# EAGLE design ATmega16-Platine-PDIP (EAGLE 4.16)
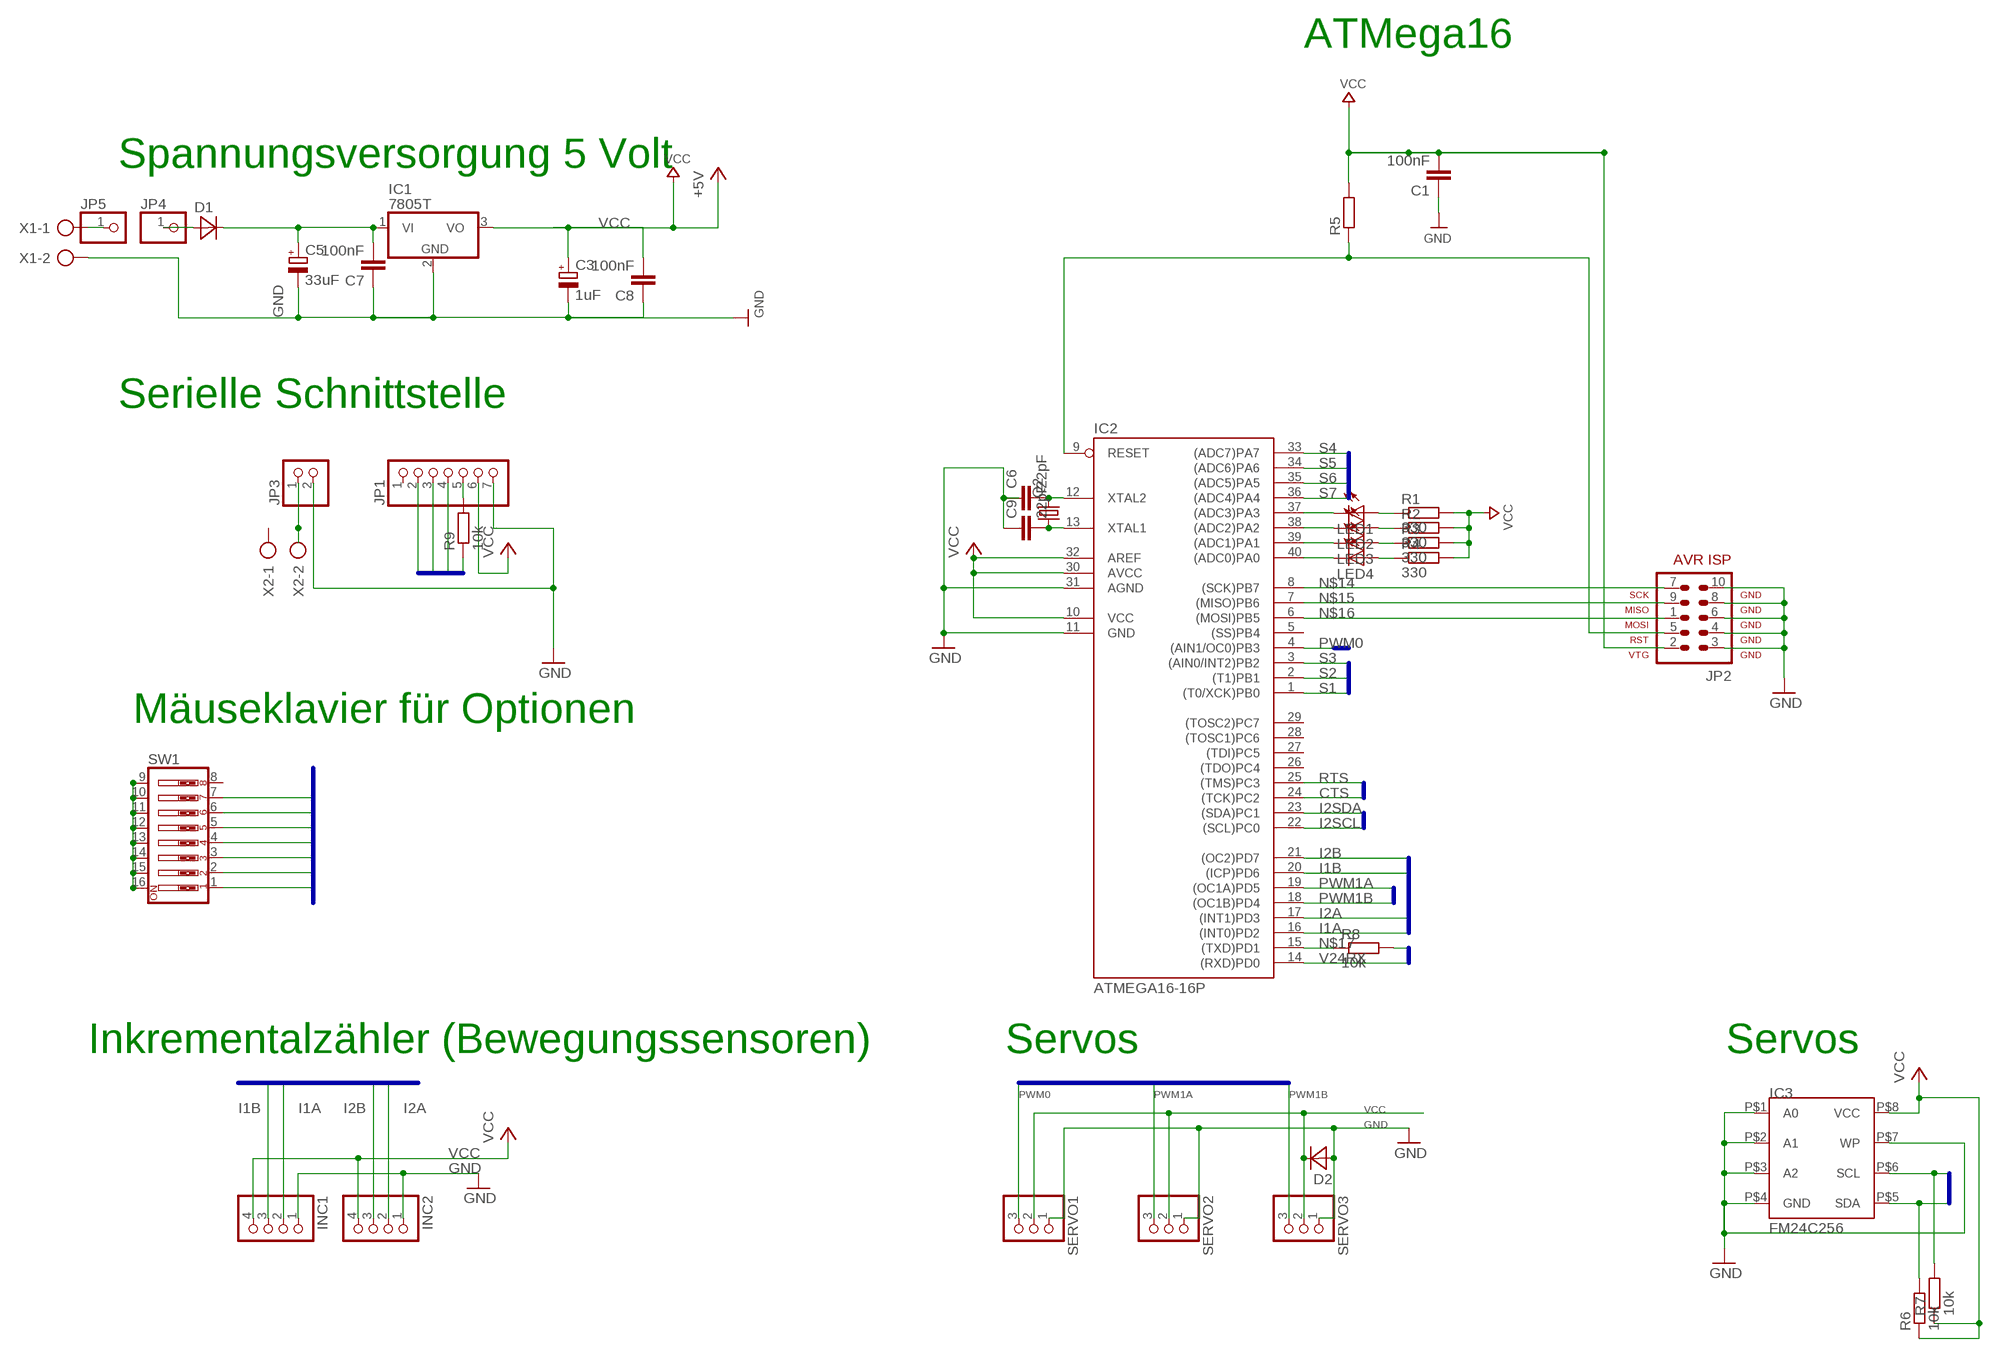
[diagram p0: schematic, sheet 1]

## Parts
C1  100nF  C2.5/2  [C2.5-2]
C3  1uF  CPOL-EUE2.5-5  [E2,5-5]
C5  33uF  CPOL-EUE2.5-5  [E2,5-5]
C6  22pF  C2.5/2  [C2.5-2]
C7  100nF  C2.5/2  [C2.5-2]
C8  100nF  C2.5/2  [C2.5-2]
C9  22pF  C2.5/2  [C2.5-2]
D1  DIODE-10  [D-10]
D2  DIODE-10  [D-10]
IC1  7805T  [TO220H]
IC2  ATMEGA16-16P  [DIL40]
IC3  FM24C256  [EIAJ-SOIC-8]
INC1  PINHD-1X4  [1X04]
INC2  PINHD-1X4  [1X04]
JP1  PINHD-1X7  [1X07]
JP2  AVR-ISP-10  [AVR-ISP-10]
JP3  PINHD-1X2  [1X02]
JP4  PINHD-1X1  [1X01]
JP5  PINHD-1X1  [1X01]
LED1  LED5MM  [LED5MM]
LED2  LED5MM  [LED5MM]
LED3  LED5MM  [LED5MM]
LED4  LED5MM  [LED5MM]
Q2  CRYTALHC49S  [HC49/S]
R1  330  R-EU_M1206  [M1206]
R2  330  R-EU_M1206  [M1206]
R3  330  R-EU_M1206  [M1206]
R4  330  R-EU_M1206  [M1206]
R5  R-EU_M1206  [M1206]
R6  10k  R-EU_M1206  [M1206]
R7  10k  R-EU_M1206  [M1206]
R8  10k  R-EU_M1206  [M1206]
R9  10k  R-EU_M1206  [M1206]
SERVO1  PINHD-1X3  [1X03]
SERVO2  PINHD-1X3  [1X03]
SERVO3  PINHD-1X3  [1X03]
SW1  SW_DIP-8  [EDG-08]
X1  AK500/2  [AK500/2]
X2  AK500/2  [AK500/2]

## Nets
/RESET: IC2.9(RESET) JP2.5 R5.1
CTS: IC2.24((TCK)PC2) JP1.2
GND: C1.1 C3.- C5.- C6.1 C7.1 C8.1 C9.1 D2.1(A) IC1.2(GND) IC2.11(GND) IC2.31(AGND) IC3.P$1(A0) IC3.P$2(A1) IC3.P$3(A2) IC3.P$4(GND) IC3.P$7(WP) INC1.1 INC2.1 JP1.7 JP2.3 JP2.4 JP2.6 JP2.8 JP2.10 JP3.2 SERVO1.1 SERVO2.1 SERVO3.1 SW1.9 SW1.10 SW1.11 SW1.12 SW1.13 SW1.14 SW1.15 SW1.16 X1.2
I1A: IC2.16((INT0)PD2) INC1.2
I1B: IC2.20((ICP)PD6) INC1.3
I2A: IC2.17((INT1)PD3) INC2.2
I2B: IC2.21((OC2)PD7) INC2.3
I2SCL: IC2.22((SCL)PC0) IC3.P$6(SCL) R7.2
I2SDA: IC2.23((SDA)PC1) IC3.P$5(SDA) R6.2
N$1: LED1.A R1.1
N$2: LED2.A R2.1
N$3: C6.2 IC2.12(XTAL2) Q2.2
N$4: C9.2 IC2.13(XTAL1) Q2.1
N$5: IC2.37((ADC3)PA3) LED1.K(C)
N$6: LED3.A R3.1
N$7: LED4.A R4.1
N$8: IC2.38((ADC2)PA2) LED2.K(C)
N$9: D1.1(A) JP4.1
N$10: IC2.39((ADC1)PA1) LED3.K(C)
N$11: IC2.40((ADC0)PA0) LED4.K(C)
N$12: C5.+ C7.2 D1.2(K) IC1.1(VI)
N$13: JP5.1 X1.1
N$14: IC2.8((SCK)PB7) JP2.7
N$15: IC2.7((MISO)PB6) JP2.9
N$16: IC2.6((MOSI)PB5) JP2.1
N$17: IC2.15((TXD)PD1) R8.1
N$18: JP3.1 X2.2
N$19: JP1.5 R9.2
PWM0: IC2.4((AIN1/OC0)PB3) SERVO1.3
PWM1A: IC2.19((OC1A)PD5) SERVO2.3
PWM1B: IC2.18((OC1B)PD4) SERVO3.3
RTS: IC2.25((TMS)PC3) R9.1
S1: IC2.1((T0/XCK)PB0) SW1.1
S2: IC2.2((T1)PB1) SW1.2
S3: IC2.3((AIN0/INT2)PB2) SW1.3
S4: IC2.33((ADC7)PA7) SW1.4
S5: IC2.34((ADC6)PA6) SW1.5
S6: IC2.35((ADC5)PA5) SW1.6
S7: IC2.36((ADC4)PA4) SW1.7
V24RX: IC2.14((RXD)PD0) JP1.3
V24TX: JP1.4 R8.2
VCC: C1.2 C3.+ C8.2 D2.2(K) IC1.3(VO) IC2.10(VCC) IC2.30(AVCC) IC2.32(AREF) IC3.P$8(VCC) INC1.4 INC2.4 JP1.6 JP2.2 R1.2 R2.2 R3.2 R4.2 R5.2 R6.1 R7.1 SERVO1.2 SERVO2.2 SERVO3.2 ; supply symbol labelled +5V
Unconnected: IC2.5((SS)PB4) IC2.26((TDO)PC4) IC2.27((TDI)PC5) IC2.28((TOSC1)PC6) IC2.29((TOSC2)PC7) JP1.1 SW1.8 X2.1

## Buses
PWM0,PWM1A,PWM1B
V24RX,V24TX,RTS,CTS
I1A,I1B,I2A,I2B
I2SCL,I2SDA
S1,S2,S3,S4,S5,S6,S7

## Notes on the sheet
- ATMega16
- Spannungsversorgung 5 Volt
- Serielle Schnittstelle
- Mäuseklavier für Optionen
- Servos | Servos
- Inkrementalzähler (Bewegungssensoren)

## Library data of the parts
C1 C6-C9 = capacitor-wima:C: CAPACITOR
C3 C5 = rcl:CPOL-EU: POLARIZED CAPACITOR, European symbol
D1 D2 = discrete:DIODE-10
IC1 = linear:78*: Positive VOLTAGE REGULATOR
IC2 = avr:ATMEGA16*P: MICROCONTROLLER 16 Kbytes FLASH 1 kbytes SRAM 512 bytes EEPROM USART 8-channel 10 bit ADC
IC3 = ramtron:FM24C256
INC1 INC2 = pinhead:PINHD-1X4: PIN HEADER
JP1 = pinhead:PINHD-1X7: PIN HEADER
JP2 = atmel_3:AVR-ISP-10: AVR ISP-10 Serial Programming Header
JP3 = pinhead:PINHD-1X2: PIN HEADER
JP4 JP5 = pinhead:PINHD-1X1: PIN HEADER
LED1-LED4 = LED:LED: LED
Q2 = crystal:CRYTAL: CRYSTAL
R1-R9 = rcl:R-EU_: RESISTOR, European symbol
SERVO1-SERVO3 = pinhead:PINHD-1X3: PIN HEADER
SW1 = special:SW_DIP-8: DIP SWITCH
X1 X2 = con-ptr500:AK500/2: CONNECTOR

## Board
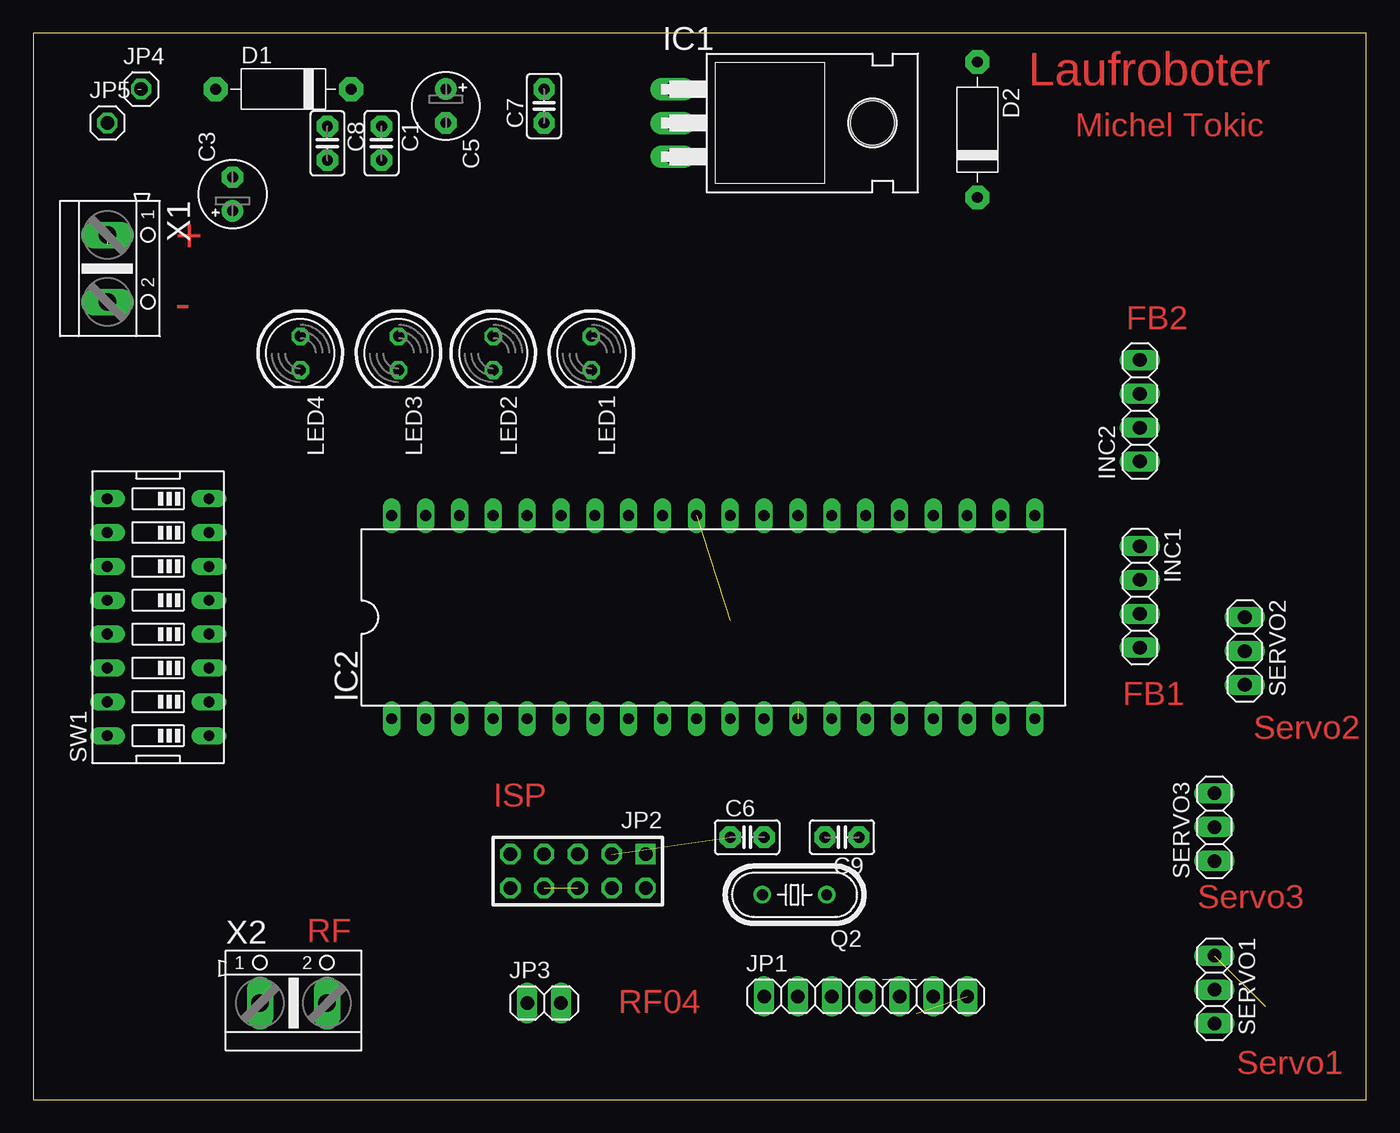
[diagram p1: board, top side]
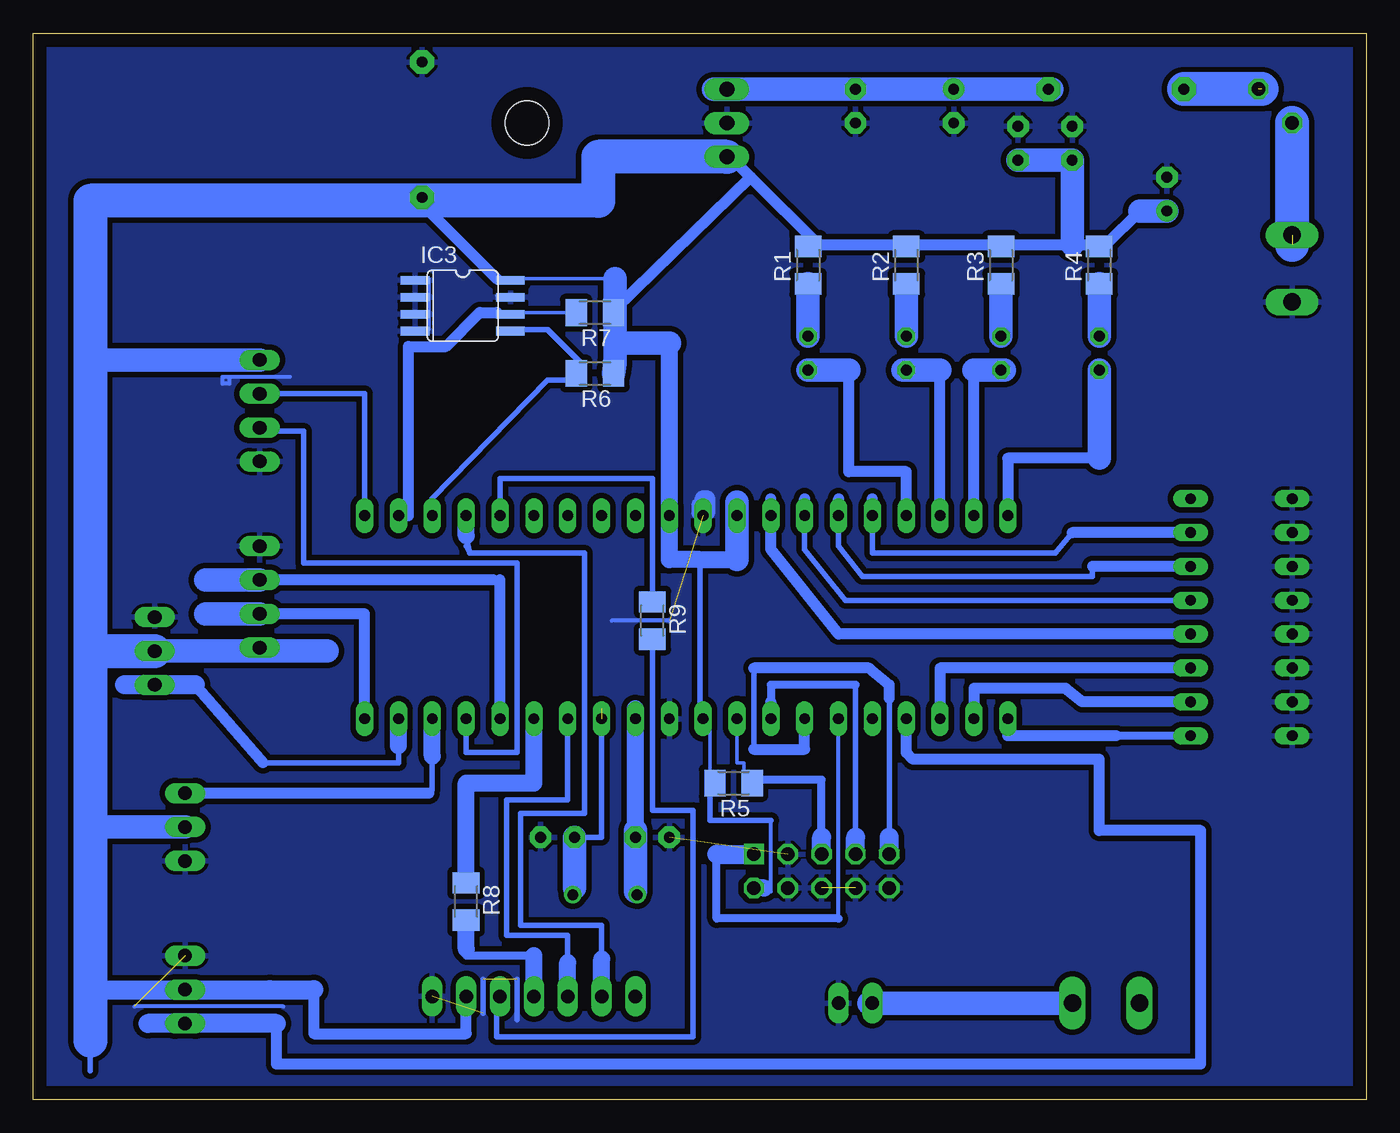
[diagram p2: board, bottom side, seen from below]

Size 100 x 80 mm. Coordinates in mm from the lower left corner, seen from the top.
Outline: 0,0 100,0 100,80 0,80 0,0
Copper layers (1*16): Top 0.035mm / dielectric 1.5mm / Bottom 0.035mm
Design rules "default": minimum track width 10mil, minimum drill 24mil, track to track 16mil, track to pad 16mil, pad to pad 16mil, via to via 16mil, smd to smd 16mil, copper to edge 40mil, drill to drill 16mil, minimum pad ring 10mil, minimum via ring 8mil, stop-mask expansion 4mil, vias tented up to drill 0mil, thermal gap 10mil

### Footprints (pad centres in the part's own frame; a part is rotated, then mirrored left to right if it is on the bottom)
C2.5-2 = drill 0.813 pad 1.6 octagon: 1 -1.27,0; 2 1.27,0
E2,5-5 = drill 0.813 pad 1.6 round: + -1.27,0 | drill 0.813 pad 1.6 octagon: - 1.27,0
D-10 = drill 0.813 pad 1.778 octagon: 1 -5.08,0; 2 5.08,0
TO220H = drill 1.118 long: 1 -2.54,-10.16; 2 0,-10.16; 3 2.54,-10.16 | hole 3.302: 0,4.826
DIL40 = drill 0.813 long: 1 -24.13,-7.62; 2 -21.59,-7.62; 3 -19.05,-7.62; 4 -16.51,-7.62; 5 -13.97,-7.62; 6 -11.43,-7.62; 7 -8.89,-7.62; 8 -6.35,-7.62; 9 -3.81,-7.62; 10 -1.27,-7.62; 11 1.27,-7.62; 12 3.81,-7.62; 13 6.35,-7.62; 14 8.89,-7.62; 15 11.43,-7.62; 16 13.97,-7.62; 17 16.51,-7.62; 18 19.05,-7.62; 19 21.59,-7.62; 20 24.13,-7.62; 21 24.13,7.62; 22 21.59,7.62; 23 19.05,7.62; 24 16.51,7.62; 25 13.97,7.62; 26 11.43,7.62; 27 8.89,7.62; 28 6.35,7.62; 29 3.81,7.62; 30 1.27,7.62; 31 -1.27,7.62; 32 -3.81,7.62; 33 -6.35,7.62; 34 -8.89,7.62; 35 -11.43,7.62; 36 -13.97,7.62; 37 -16.51,7.62; 38 -19.05,7.62; 39 -21.59,7.62; 40 -24.13,7.62
EIAJ-SOIC-8 = smd 0.65 x 2.15: P$1 -1.905,-3.576; P$2 -0.635,-3.576; P$3 0.635,-3.576; P$4 1.905,-3.576; P$5 1.905,3.576; P$6 0.635,3.576; P$7 -0.635,3.576; P$8 -1.905,3.576
1X04 = drill 1.016 long: 1 -3.81,0; 2 -1.27,0; 3 1.27,0; 4 3.81,0
1X07 = drill 1.016 long: 1 -7.62,0; 2 -5.08,0; 3 -2.54,0; 4 0,0; 5 2.54,0; 6 5.08,0; 7 7.62,0
AVR-ISP-10 = drill 1.016 square: 1 -5.08,-1.27 | drill 1.016 octagon: 2 -5.08,1.27; 3 -2.54,-1.27; 4 -2.54,1.27; 5 0,-1.27; 6 0,1.27; 7 2.54,-1.27; 8 2.54,1.27; 9 5.08,-1.27; 10 5.08,1.27
1X02 = drill 1.016 long: 1 -1.27,0; 2 1.27,0
1X01 = drill 1.016 octagon: 1 0,0
LED5MM = drill 0.813 octagon: A -1.27,0; K 1.27,0
HC49/S = drill 0.813 round: 1 -2.413,0; 2 2.413,0
M1206 = smd 1.6 x 2: 1 -1.4,0; 2 1.4,0
1X03 = drill 1.016 long: 1 -2.54,0; 2 0,0; 3 2.54,0
EDG-08 = drill 0.813 long: 1 -8.89,-3.81; 2 -6.35,-3.81; 3 -3.81,-3.81; 4 -1.27,-3.81; 5 1.27,-3.81; 6 3.81,-3.81; 7 6.35,-3.81; 8 8.89,-3.81; 9 8.89,3.81; 10 6.35,3.81; 11 3.81,3.81; 12 1.27,3.81; 13 -1.27,3.81; 14 -3.81,3.81; 15 -6.35,3.81; 16 -8.89,3.81
AK500/2 = drill 1.321 long: 1 -2.515,0; 2 2.515,0

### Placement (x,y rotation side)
C1  26.12,71.75 270 top
C3  14.95,67.94 90 top
C5  30.95,74.54 270 top
C6  53.56,19.68 0 top
C7  38.32,74.54 90 top
C8  22.06,71.75 270 top
C9  60.67,19.68 180 top
D1  18.76,75.81 0 top
D2  70.83,72.77 270 top
IC1  58.13,73.27 270 top
IC2  51.02,36.19 0 top
IC3  67.78,59.56 270 bottom
INC1  83.02,37.71 270 top
INC2  83.02,51.68 90 top
JP1  62.45,7.74 0 top
JP2  40.86,17.14 180 top
JP3  38.32,7.23 0 top
JP4  8.09,75.81 0 top
JP5  5.55,73.27 0 top
LED1  41.87,56 270 top
LED2  34.51,56 270 top
LED3  27.39,56 270 top
LED4  20.03,56 270 top
Q2  57.11,15.36 180 top
R1  41.87,62.61 90 bottom
R2  34.51,62.61 90 bottom
R3  27.39,62.61 90 bottom
R4  20.03,62.61 90 bottom
R5  47.46,23.74 180 bottom
R6  57.87,54.48 180 bottom
R7  57.87,59.05 180 bottom
R8  67.53,14.85 270 bottom
R9  53.56,35.94 270 bottom
SERVO1  88.61,8.25 270 top
SERVO2  90.89,33.65 270 top
SERVO3  88.61,20.44 90 top
SW1  9.36,36.19 90 top
X1  5.55,62.35 270 top
X2  19.52,7.23 0 top

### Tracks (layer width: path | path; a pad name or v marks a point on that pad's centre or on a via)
/RESET
  Bottom 0.254: IC2.9 47.21,25.27 46.7,25.27 46.7,24.51 R5.1 46.19,24 | 40.86,18.16 JP2.5
  Bottom 0.61: 40.86,19.68 40.86,24 46.19,24
  Bottom 1.422: JP2.5 40.86,19.68
CTS
  Bottom 0.406: 67.27,41.02 58.64,41.02 58.64,21.46 63.46,21.46 63.46,13.08 57.37,13.08 57.37,10.54 | 67.27,41.02 67.53,41.52 | 67.27,41.02 67.53,42.29 | JP1.2 57.37,6.98
  Bottom 1.27: 67.53,42.29 IC2.24 | JP1.2 57.37,10.54
GND  (6 unrouted)
  Bottom 0.254: 70.32,59.05 70.32,57.78 IC3.P$4 | IC3.P$7 65.24,60.32 | 70.32,60.32 70.32,61.59 IC3.P$1 | 70.32,59.05 70.32,60.32 | IC3.P$3 70.32,59.05 | 70.32,60.32 IC3.P$2 | IC1.2 47.46,73.02 | C7.1 38.57,73.02
  Bottom 0.305: 80.73,54.22 85.31,54.22 | 85.31,54.22 85.81,54.22 85.81,53.72 85.31,53.72 85.31,54.22 | 81.24,6.98 92.42,6.98 | 52.29,35.94 56.6,35.94
  Bottom 0.406: 63.72,5.96 63.72,9.01 | 66.26,6.47 66.26,9.01
  Bottom 1.27: IC2.31 49.75,45.08 49.49,45.08 49.49,44.06 50,44.06 50,44.57
  pour Bottom: 0.22,79.88 99.53,79.88 99.53,0.12 0.47,0.12 0.47,79.88 0.72,79.88
I1A
  Bottom 0.406: 64.99,38.98 65.49,38.98
  Bottom 0.813: 64.99,38.98 64.99,31.36 IC2.16 | 65.49,38.98 INC1.2
  Bottom 1.778: INC1.2 87.08,38.98
I1B
  Bottom 0.813: INC1.3 75.15,36.44 75.15,31.62 IC2.20
  Bottom 1.778: INC1.3 87.08,36.44
I2A
  Bottom 0.406: IC2.17 67.53,26.03 63.72,26.03 63.72,40.25 79.72,40.25 79.72,50.16 83.02,50.16 INC2.2
I2B
  Bottom 0.406: IC2.21 75.15,52.95 INC2.3
I2SCL
  Bottom 0.254: 58.89,59.05 R7.2 63.97,59.05 IC3.P$6 65.24,59.05
  Bottom 0.813: 65.24,59.05 66.51,59.05 69.05,56.51 71.84,56.51 71.84,43.81 IC2.22
I2SDA
  Bottom 0.254: 58.89,55.24 R6.2 58.89,53.97 | 63.97,57.78 IC3.P$5 | 70.07,45.08 IC2.23
  Bottom 0.406: 58.89,55.24 61.43,57.78 63.97,57.78 | 70.07,45.08 61.43,53.97 58.89,53.97
N$1
  Bottom 0.406: R1.1 41.87,61.34
  Bottom 1.778: LED1.A R1.1
N$2
  Bottom 0.254: 34.51,61.08 R2.1
  Bottom 1.778: LED2.A 34.51,61.08
N$3
  Bottom 0.254: 54.83,27.3 IC2.12 | Q2.2 54.83,15.62
  Bottom 1.27: 54.83,29.33 54.83,27.3 54.83,20.19
  Bottom 1.778: 54.83,20.19 C6.2 54.83,15.62
N$4  (1 unrouted)
  Bottom 0.254: Q2.1 59.4,15.87
  Bottom 0.406: 57.37,29.33 57.37,19.68 C9.2
  Bottom 1.778: 59.4,15.87 C9.2
N$5
  Bottom 0.813: 38.82,54.73 38.82,47.11 34.51,47.11 IC2.37
  Bottom 1.778: 38.82,54.73 LED1.K
N$6
  Bottom 0.254: 27.39,61.08 R3.1
  Bottom 1.778: LED3.A 27.39,61.08
N$7
  Bottom 1.778: LED4.A R4.1
N$8
  Bottom 0.254: 34.76,54.73 LED2.K
  Bottom 0.813: IC2.38 31.97,54.73
  Bottom 1.778: 31.97,54.73 34.76,54.73
N$9  (1 unrouted)
  Bottom 2.54: 7.84,75.81 D1.1
N$10
  Bottom 0.254: 27.14,54.73 LED3.K
  Bottom 0.813: IC2.39 29.43,54.73
  Bottom 1.778: 29.43,54.73 27.14,54.73
N$11
  Bottom 0.813: 20.03,48.13 26.89,48.13 IC2.40
  Bottom 1.778: 20.03,48.13 LED4.K
N$12
  Bottom 0.254: 48.98,75.81 IC1.1 | C7.2 37.55,75.81 | D1.2 23.58,75.81 23.33,75.56
  Bottom 1.778: C7.2 C5.+ 23.58,75.81 | 37.55,75.81 48.98,75.81
N$13  (1 unrouted)
  Bottom 2.54: 5.55,64.13 JP5.1
N$14
  Bottom 0.254: 38.32,18.16 JP2.7
  Bottom 0.406: 38.32,19.68 38.32,31.11
  Bottom 0.61: 44.67,29.84 44.67,31.11 38.32,31.11
  Bottom 0.813: 44.67,29.84 IC2.8
  Bottom 1.422: JP2.7 38.32,19.68
N$15
  Bottom 0.254: 35.78,18.16 JP2.9
  Bottom 0.406: 45.94,32.38 45.94,26.28 | 35.78,19.68 35.78,30.09
  Bottom 0.813: 45.94,26.28 42.13,26.28 IC2.7 | 45.94,32.38 37.3,32.38 35.78,31.11 35.78,30.09
  Bottom 1.422: JP2.9 35.78,19.68
N$16
  Bottom 0.305: 39.59,13.58 IC2.6
  Bottom 0.61: 39.59,13.58 48.73,13.58 48.73,18.41
  Bottom 1.422: 48.73,18.41 JP2.1
N$17
  Bottom 1.27: R8.1 67.53,23.74 62.45,23.74 IC2.15
N$18
  Bottom 1.778: 37.3,7.23 JP3.1 X2.2
N$19
  Bottom 0.406: JP1.5 65.24,7.74 65.24,4.69 50.51,4.69 50.51,21.71 53.56,21.71 R9.2
PWM0
  Bottom 0.813: 81.75,5.71 81.75,2.66 12.41,2.66 12.41,20.19 20.03,20.19 20.03,25.52 34,25.52 34.51,26.03 IC2.4 34.51,28.82
  Bottom 1.422: 81.75,5.71 SERVO1.3 91.4,5.71
PWM1A
  Bottom 0.406: 72.61,26.54 72.61,25.27 82.77,25.27
  Bottom 0.813: 82.77,25.27 87.85,31.11
  Bottom 1.27: 72.61,26.54 IC2.19
  Bottom 1.422: 87.85,31.11 SERVO2.3 93.18,31.11
PWM1B
  Bottom 0.406: 70.07,25.78 70.07,23.24 70.32,22.98
  Bottom 0.813: 70.32,22.98 SERVO3.3
  Bottom 1.27: 70.07,25.78 IC2.18
RTS
  Bottom 0.406: R9.1 53.56,46.6 64.99,46.6 IC2.25
S1
  Bottom 0.61: SW1.1 18.76,27.3
  Bottom 0.813: 18.76,27.3 26.89,27.3 IC2.1
S2
  Bottom 0.813: IC2.2 29.43,30.86 22.57,30.86 21.3,29.84 SW1.2
S3
  Bottom 0.813: IC2.3 31.97,32.38 SW1.3
S4
  Bottom 0.813: 44.67,45.08 IC2.33 44.67,41.27 39.59,34.92 SW1.4 12.92,34.92
S5
  Bottom 0.406: IC2.34 42.13,41.27 39.08,37.46 SW1.5
  Bottom 0.813: IC2.34 42.13,45.08 | 12.92,37.46 SW1.5
S6
  Bottom 0.406: 20.54,40 20.54,39.24 37.81,39.24 39.59,41.52 IC2.35
  Bottom 0.813: IC2.35 39.59,45.08 | 12.92,40 SW1.6 | 12.92,40 20.54,40 | 12.92,40 12.92,39.75
S7
  Bottom 0.406: 22.06,42.54 23.33,41.02 37.05,41.02 IC2.36
  Bottom 0.813: IC2.36 37.05,45.08 | 12.92,42.54 SW1.7 | 12.92,42.54 22.06,42.54 | 12.92,42.54 12.92,42.29
V24RX
  Bottom 0.406: IC2.14 59.91,22.47 64.48,22.47 64.48,12.31 59.91,12.31 59.91,10.28
  Bottom 1.27: JP1.3 59.91,10.28
V24TX
  Bottom 0.61: 62.45,10.79 67.53,10.79 67.53,11.3
  Bottom 1.27: JP1.4 62.45,10.79 | 67.53,11.3 R8.2
VCC
  Bottom 0.254: 65.24,61.59 IC3.P$8 63.97,61.59 56.35,61.59 | 71.59,67.94 D2.2 | 19.52,64.13 R4.2 20.79,64.13 | 47.46,70.48 IC1.3 | 41.11,64.13 R1.2 | 27.14,64.13 R3.2 | 34.76,64.13 R2.2 | 56.35,59.3 R7.1 | 50,29.84 IC2.10 49.24,28.06 49.24,23.49 R5.2 | 77.94,33.65 INC1.4
  Bottom 0.305: 44.67,15.87 44.67,20.95 | 44.67,15.62 44.67,15.87 | 44.67,15.87 45.17,15.87
  Bottom 0.406: 50,29.84 50,40.51 | SERVO2.2 90.89,33.9 | 49.24,23.49 49.24,20.95 44.67,20.95 | 95.72,4.44 95.72,2.15
  Bottom 0.61: 82.26,8.25 82.26,8
  Bottom 0.813: 65.24,61.59 71.59,67.94 | 19.52,64.13 16.98,66.67 | 20.79,64.13 22.06,64.13 27.14,64.13 34.76,64.13 41.11,64.13 46.19,69.21 | 46.19,69.21 47.46,70.48 | 56.35,59.3 46.19,69.21 | JP1.6 67.53,4.95 78.96,4.95 78.96,8.25
  Bottom 1.27: 47.21,40.51 50,40.51 52.29,40.51 IC2.30 52.29,56.76 | 45.17,15.87 JP2.2
  Bottom 1.422: 95.72,8.25 SERVO1.2 82.26,8.25 78.96,8.25
  Bottom 1.778: C1.2 C8.2 22.06,64.13 | 56.35,56.76 56.35,59.3 56.35,61.59 | 56.35,56.76 56.35,55.24 R6.1 | 16.98,66.67 C3.+ | 47.21,40.51 IC2.32 47.21,44.83 | SERVO2.2 77.94,33.65 | 52.29,56.76 56.35,56.76 | 95.72,55.49 INC2.4 | 95.72,20.44 SERVO3.2
  Bottom 2.54: IC1.3 57.62,70.73 57.62,67.43 95.72,67.43 95.72,55.49 95.72,33.65 | 95.72,4.44 95.72,8.25 95.72,20.44 95.72,33.65 | 95.72,33.65 SERVO2.2

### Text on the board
Top: Laufroboter | Michel Tokic | + | - | FB2 | FB1 | Servo2 | ISP | Servo3 | RF | RF04 | Servo1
